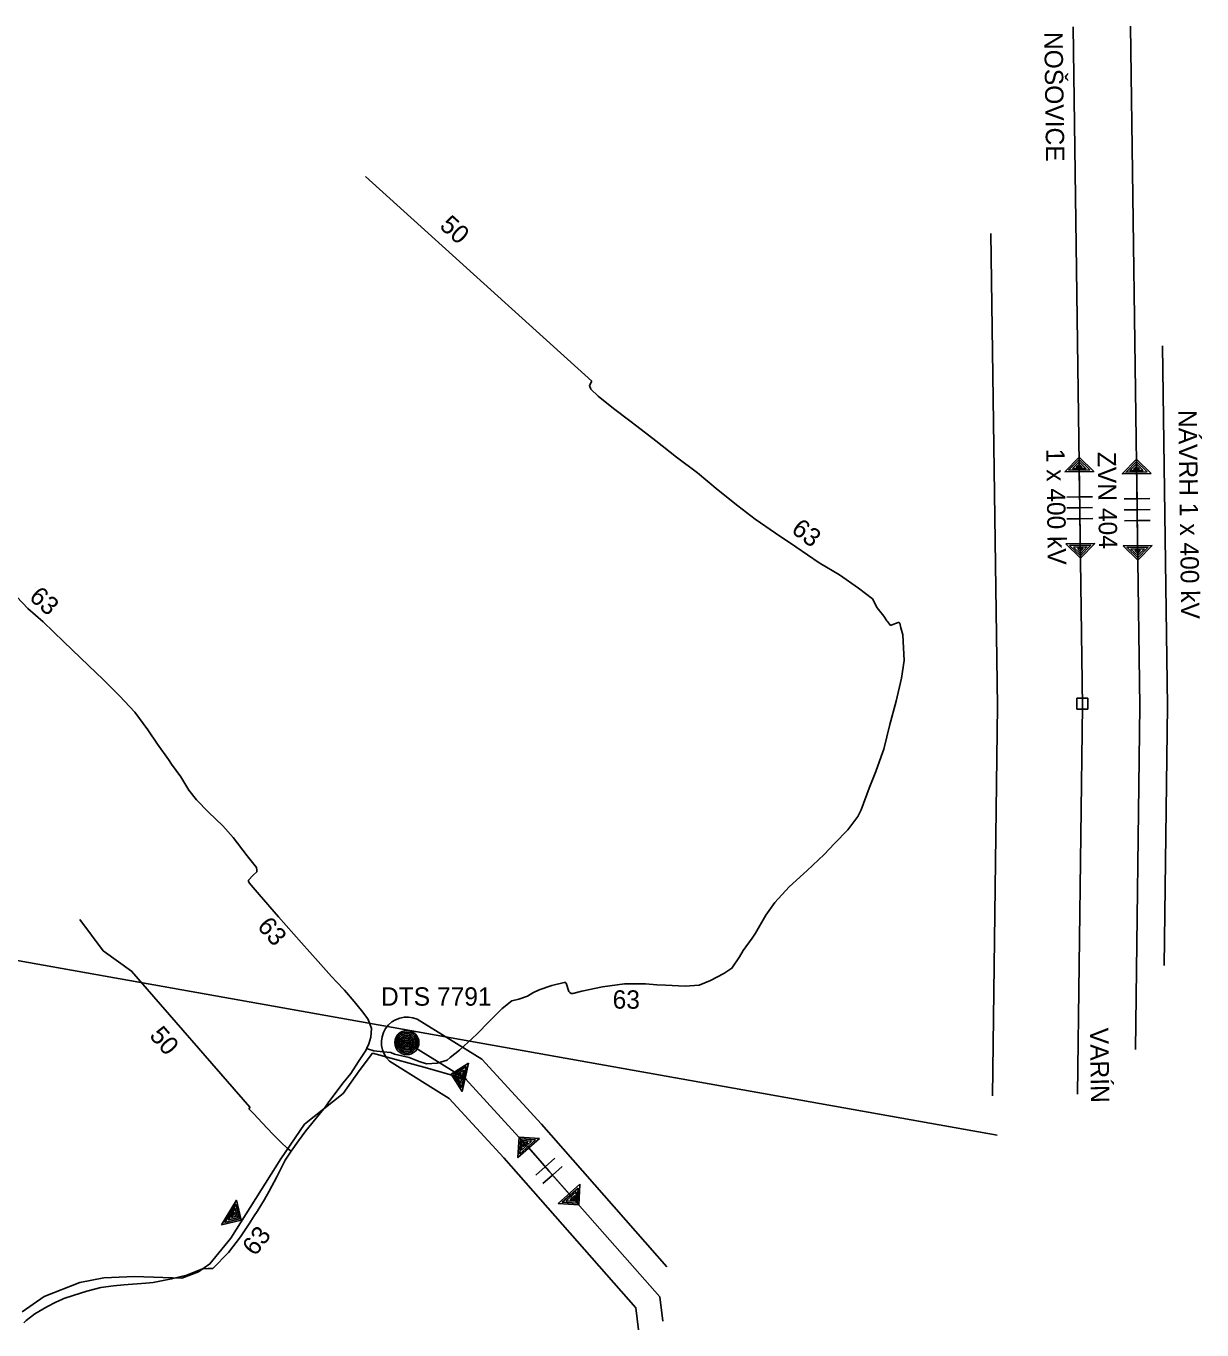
# Model space of a CAD drawing. Extents: x -444841 to -429545, y -1135312 to -1129851.
# Drawn here: x -441113 to -440601, y -1131774 to -1131206 of the extents above; entities that cross this region are included whole.
import ezdxf

# ---------------------------------------------------------------- set-up
doc = ezdxf.new("R2010")
doc.units = 0
for name, color, linetype in [('Vrstva 10', 7, 'Continuous'), ('Vrstva 11', 7, 'Continuous'), ('Vrstva 13', 7, 'Continuous'), ('Vrstva 15', 7, 'Continuous'), ('Vrstva 17', 7, 'Continuous'), ('Vrstva 18', 7, 'Continuous'), ('Vrstva 27', 7, 'Continuous'), ('Vrstva 30', 7, 'Continuous'), ('Vrstva 35', 7, 'Continuous'), ('Vrstva 38', 7, 'Continuous'), ('Vrstva 59', 7, 'Continuous'), ('Vrstva 9', 7, 'Continuous')]:
    doc.layers.add(name, color=color, linetype=linetype)

msp = doc.modelspace()

# ---------------------------------------------------------------- linework, layer by layer
at = {"layer": 'Vrstva 10'}
for p, q in [((-440886.93, -1131702.64), (-440891.13, -1131706.34)), ((-440882.73, -1131698.94), (-440886.93, -1131702.64)), ((-440879.58, -1131702.51), (-440883.79, -1131706.21)), ((-440883.79, -1131706.21), (-440887.99, -1131709.91))]:
    msp.add_line(p, q, dxfattribs=at)
for points in [[(-440835.75, -1131769.83), (-440837.12, -1131759.22), (-440896.8, -1131691.43), (-440921.67, -1131664.33), (-440947.21, -1131648.56)], [(-440894.15, -1131694.44), (-440885.36, -1131704.43), (-440876.57, -1131714.41)]]:
    msp.add_lwpolyline(points, dxfattribs=at)
for points in [[(-440889.42, -1131690.28), (-440898.87, -1131698.6), (-440898.31, -1131689.71)], [(-440891.15, -1131690.87), (-440898.07, -1131696.96), (-440897.65, -1131690.46)], [(-440892.88, -1131691.46), (-440897.26, -1131695.32), (-440897, -1131691.2)], [(-440894.61, -1131692.05), (-440896.46, -1131693.68), (-440896.35, -1131691.94)], [(-440871.84, -1131710.25), (-440872.41, -1131719.14), (-440881.3, -1131718.57)], [(-440872.65, -1131711.89), (-440873.06, -1131718.39), (-440879.57, -1131717.98)], [(-440873.45, -1131713.53), (-440873.72, -1131717.65), (-440877.84, -1131717.39)], [(-440874.26, -1131715.17), (-440874.37, -1131716.91), (-440876.1, -1131716.8)]]:
    msp.add_lwpolyline(points, close=True, dxfattribs=at)
at = {"layer": 'Vrstva 11'}
for radius in [5.25, 4.55, 3.85, 3.15, 2.45, 1.75, 1.05, 0.35]:
    msp.add_circle((-440947.21, -1131648.57), radius, dxfattribs=at)
at = {"layer": 'Vrstva 15'}
for points in [[(-440692.94, -1131296.37), (-440690.11, -1131502.12), (-440692.33, -1131671.75)], [(-440617.58, -1131614.95), (-440616.1, -1131502.09), (-440618.26, -1131345.26)], [(-440833.99, -1131746.13), (-440888.61, -1131684.08), (-440914.59, -1131655.77), (-440942.69, -1131638.42)], [(-440954.79, -1131656.67), (-440928.74, -1131672.89), (-440904.98, -1131698.78), (-440847.6, -1131763.96), (-440846.35, -1131773.63)]]:
    msp.add_lwpolyline(points, dxfattribs=at)
msp.add_arc((-440947.21, -1131648.56), 11.1, 66.0025, 226.9228, dxfattribs=at)
at = {"layer": 'Vrstva 17'}
msp.add_lwpolyline([(-440630.06, -1131651.58), (-440628.11, -1131502.1), (-440632.18, -1131206.12)], dxfattribs=at)
at = {"layer": 'Vrstva 18'}
msp.add_lwpolyline([(-441114.72, -1131765.75), (-441105.1, -1131759.04), (-441089.51, -1131753.06), (-441079.08, -1131750.95), (-441065.74, -1131750.44), (-441045.19, -1131751.17), (-441037.9, -1131748.4), (-441032.95, -1131744.9), (-441023.91, -1131733.68), (-441002.04, -1131699.13), (-440991.84, -1131684.11), (-440974.93, -1131670.7), (-440967.93, -1131660.79), (-440962.1, -1131653.21), (-440938.2, -1131659.63), (-440921.07, -1131664.65)], dxfattribs=at)
for points in [[(-440920.34, -1131657.54), (-440923.19, -1131669.82), (-440927.9, -1131662.26)], [(-440921.41, -1131659.03), (-440923.49, -1131668.01), (-440926.94, -1131662.48)], [(-440922.47, -1131660.52), (-440923.79, -1131666.21), (-440925.97, -1131662.7)], [(-440923.53, -1131662.01), (-440924.09, -1131664.4), (-440925.01, -1131662.93)], [(-441027.92, -1131727.95), (-441021.41, -1131717.16), (-441019.27, -1131725.81)], [(-441026.45, -1131726.86), (-441021.69, -1131718.97), (-441020.12, -1131725.3)], [(-441024.98, -1131725.78), (-441021.96, -1131720.78), (-441020.97, -1131724.79)], [(-441023.51, -1131724.69), (-441022.24, -1131722.59), (-441021.82, -1131724.28)]]:
    msp.add_lwpolyline(points, close=True, dxfattribs=at)
at = {"layer": 'Vrstva 27'}
for points in [[(-440734.19, -1131500), (-440734.17, -1131499.94), (-440731.85, -1131490.01), (-440730.67, -1131482.24), (-440731, -1131476.75), (-440731.26, -1131471.13), (-440732.11, -1131468.09), (-440732.67, -1131466.07), (-440733.01, -1131465.78), (-440733.29, -1131465.73), (-440736.41, -1131466.94), (-440736.74, -1131466.87), (-440737.15, -1131466.45), (-440738.01, -1131465.26), (-440738.28, -1131464.95), (-440739.53, -1131463.02), (-440742.46, -1131459.36), (-440744.56, -1131455.4), (-440750.55, -1131450.74), (-440758.88, -1131445.03), (-440767.75, -1131439.72), (-440777.92, -1131432.84), (-440786.75, -1131426.83), (-440795.64, -1131420.77), (-440803.1, -1131414.95), (-440811.7, -1131408.14), (-440820.7, -1131400.63), (-440829.77, -1131393.74), (-440838.85, -1131386.59), (-440847.1, -1131380.3), (-440850.1, -1131377.96), (-440857.21, -1131372.58), (-440863.95, -1131367.2), (-440867.14, -1131364.23), (-440867.72, -1131362.53), (-440866.7, -1131360.69)], [(-441070.07, -1131500), (-441072.1, -1131497.84), (-441079.4, -1131490.47), (-441085.86, -1131484.44), (-441096.58, -1131474.12), (-441105.52, -1131465.46), (-441112.2, -1131459.56), (-441119.53, -1131451.89), (-441127.19, -1131444.62), (-441136.54, -1131435.94), (-441141.11, -1131431.57), (-441144.33, -1131428.63), (-441149.5, -1131424.16), (-441152.91, -1131420.45), (-441153.4, -1131420.22)], [(-440980.05, -1131619.85), (-440985.79, -1131613.32), (-440993.11, -1131605.08), (-441003.09, -1131593.79), (-441011.45, -1131584.1), (-441015.9, -1131578.99), (-441016.15, -1131578.3), (-441016.1, -1131577.93), (-441014.05, -1131575.74), (-441012.59, -1131574.19), (-441012.57, -1131573.47), (-441012.72, -1131572.41), (-441016.79, -1131567.33), (-441022.87, -1131559.34), (-441027.27, -1131554.29), (-441033.52, -1131548.22), (-441038.78, -1131542.84), (-441042.1, -1131538.7), (-441045.64, -1131532.83), (-441049.64, -1131527.32), (-441050.97, -1131525.3), (-441055.73, -1131518.7), (-441059.92, -1131512.47), (-441065.56, -1131504.81), (-441070.07, -1131500)], [(-440924.34, -1131651.81), (-440916.75, -1131644.88), (-440911.2, -1131639.3), (-440905.77, -1131633.67), (-440901.46, -1131630.43), (-440898.46, -1131629.66), (-440894.65, -1131628.29), (-440892.3, -1131626.92), (-440889.56, -1131625.63), (-440884.1, -1131623.73), (-440878.69, -1131622.39), (-440878.1, -1131622.39), (-440877.88, -1131622.66), (-440876.71, -1131626.32), (-440876.33, -1131626.75), (-440875.66, -1131627.22), (-440874.94, -1131627.22), (-440871.04, -1131626.2), (-440862.11, -1131624.35), (-440852.53, -1131622.95), (-440843.3, -1131623), (-440838.38, -1131623.48), (-440834.57, -1131623.54), (-440826.06, -1131623.95), (-440820.03, -1131623.55), (-440814.97, -1131621.6), (-440809.18, -1131618.53), (-440805.71, -1131616.19), (-440802.36, -1131611.25), (-440800.74, -1131608.52), (-440796.85, -1131603.06), (-440795.42, -1131600.87), (-440790.92, -1131593.16), (-440786.95, -1131587.63), (-440780.72, -1131580.74), (-440772.89, -1131573.68), (-440765.58, -1131566.77), (-440761.07, -1131561.96), (-440755.17, -1131555.96), (-440750.85, -1131550.12), (-440749.48, -1131547.32), (-440745.9, -1131537.81), (-440743.01, -1131530.54), (-440740.73, -1131524.02), (-440739.63, -1131520.88), (-440736.93, -1131510.07), (-440734.19, -1131500)], [(-440964.63, -1131651.04), (-440963.72, -1131649.12), (-440962.86, -1131646.19), (-440962.64, -1131642.43), (-440963.28, -1131640.47), (-440964.23, -1131638.23), (-440967.02, -1131634.58), (-440970.21, -1131630.72), (-440974.33, -1131625.8), (-440977.91, -1131622.07), (-440980.05, -1131619.85)], [(-441113.91, -1131770.51), (-441112.95, -1131769.57), (-441109.22, -1131766.69), (-441103.94, -1131763.55), (-441099.96, -1131761.58), (-441097.42, -1131760.36), (-441096.57, -1131759.96), (-441092.51, -1131758.61), (-441086.55, -1131756.78), (-441085.98, -1131756.61), (-441080.47, -1131755.1), (-441074.98, -1131754.49), (-441070.41, -1131753.99), (-441060.83, -1131753.29), (-441057.65, -1131753.06), (-441049.63, -1131751.45), (-441043.06, -1131749.74), (-441038.37, -1131747.97), (-441036.24, -1131747.02), (-441033.66, -1131746.86), (-441033.5, -1131746.9), (-441031.74, -1131746.83), (-441024.8, -1131739.89), (-441019.64, -1131733.17), (-441015.85, -1131727.48), (-441013.61, -1131723.93), (-441012.41, -1131722.03), (-441009.14, -1131716.84), (-441007.14, -1131713.22), (-441003.88, -1131707.01), (-441000.17, -1131699.7), (-440997.81, -1131696.28), (-440997.52, -1131695.86), (-440994.43, -1131691.31), (-440991.22, -1131687.04), (-440985.36, -1131679.83), (-440983.41, -1131677.42), (-440982.7, -1131676.54), (-440981.14, -1131674.3), (-440974.92, -1131666.11), (-440971.54, -1131661.98), (-440968.19, -1131656.8), (-440965.11, -1131652.06), (-440964.63, -1131651.04)], [(-440964.63, -1131651.04), (-440964.35, -1131651.24), (-440961.6, -1131652.16), (-440957.51, -1131652.63), (-440954.2, -1131652.84), (-440952.54, -1131653.61), (-440946.21, -1131655.08), (-440941.82, -1131656.8), (-440938.59, -1131657.79), (-440933.96, -1131657.52), (-440929.7, -1131656.16), (-440928.29, -1131655.06), (-440926.3, -1131653.52), (-440924.34, -1131651.81)], [(-440997.52, -1131695.86), (-440999.29, -1131694.55), (-441001.92, -1131692.05), (-441005.62, -1131688.41), (-441010.16, -1131683.47), (-441013.86, -1131679.64), (-441015.82, -1131677.54), (-441015.83, -1131677.38), (-441015.67, -1131676.92), (-441015.33, -1131676.51)], [(-441033.66, -1131746.86), (-441033.49, -1131746.69)]]:
    msp.add_lwpolyline(points, dxfattribs=at)
at = {"layer": 'Vrstva 35'}
msp.add_line((-440866.7, -1131360.69), (-440965.19, -1131271.64), dxfattribs=at)
msp.add_lwpolyline([(-441015.52, -1131676.67), (-441067.04, -1131617.45), (-441079.48, -1131608.57), (-441089.54, -1131594.95)], dxfattribs=at)
at = {"layer": 'Vrstva 59'}
msp.add_lwpolyline([(-440690.16, -1131688.83), (-443044.68, -1131269.31), (-443119.43, -1131255.99)], dxfattribs=at)
at = {"layer": 'Vrstva 9'}
for p, q in [((-440659.96, -1131411.1), (-440654.36, -1131411.03)), ((-440654.36, -1131411.03), (-440648.76, -1131410.95)), ((-440629.35, -1131411.87), (-440634.95, -1131411.94)), ((-440623.75, -1131411.79), (-440629.35, -1131411.87)), ((-440659.9, -1131415.86), (-440654.3, -1131415.79)), ((-440654.3, -1131415.79), (-440648.7, -1131415.71)), ((-440629.28, -1131416.63), (-440634.88, -1131416.7)), ((-440623.68, -1131416.55), (-440629.28, -1131416.63)), ((-440659.83, -1131420.62), (-440654.23, -1131420.55)), ((-440654.23, -1131420.55), (-440648.63, -1131420.47)), ((-440629.22, -1131421.39), (-440634.82, -1131421.46)), ((-440623.62, -1131421.31), (-440629.22, -1131421.39))]:
    msp.add_line(p, q, dxfattribs=at)
for points in [[(-440655.32, -1131670.99), (-440653.11, -1131502.1), (-440657.18, -1131206.47)], [(-440654.08, -1131431.46), (-440654.3, -1131415.79), (-440654.51, -1131400.11)], [(-440629.5, -1131400.95), (-440629.28, -1131416.63), (-440629.07, -1131432.3)]]:
    msp.add_lwpolyline(points, dxfattribs=at)
for points in [[(-440660.81, -1131400.19), (-440654.6, -1131393.81), (-440648.21, -1131400.02)], [(-440659.13, -1131399.47), (-440654.59, -1131394.8), (-440649.91, -1131399.34)], [(-440657.45, -1131398.75), (-440654.57, -1131395.79), (-440651.61, -1131398.67)], [(-440655.77, -1131398.02), (-440654.56, -1131396.78), (-440653.31, -1131397.99)], [(-440623.2, -1131400.86), (-440635.8, -1131401.03), (-440629.59, -1131394.65)], [(-440624.9, -1131400.18), (-440634.12, -1131400.31), (-440629.57, -1131395.64)], [(-440626.6, -1131399.51), (-440632.44, -1131399.59), (-440629.56, -1131396.63)], [(-440628.3, -1131398.83), (-440630.76, -1131398.86), (-440629.54, -1131397.62)], [(-440660.38, -1131431.55), (-440647.78, -1131431.38), (-440653.99, -1131437.76)], [(-440658.68, -1131432.23), (-440649.46, -1131432.1), (-440654.01, -1131436.77)], [(-440656.98, -1131432.9), (-440651.14, -1131432.82), (-440654.02, -1131435.78)], [(-440655.28, -1131433.58), (-440652.82, -1131433.55), (-440654.03, -1131434.79)], [(-440622.77, -1131432.22), (-440628.98, -1131438.6), (-440635.37, -1131432.39)], [(-440624.45, -1131432.94), (-440628.99, -1131437.61), (-440633.67, -1131433.07)], [(-440626.13, -1131433.66), (-440629.01, -1131436.62), (-440631.97, -1131433.74)], [(-440627.81, -1131434.39), (-440629.02, -1131435.63), (-440630.27, -1131434.42)], [(-440655.52, -1131503.39), (-440650.79, -1131503.39), (-440650.79, -1131498.66), (-440655.52, -1131498.66)]]:
    msp.add_lwpolyline(points, close=True, dxfattribs=at)

# ---------------------------------------------------------------- texts
at = {"layer": 'Vrstva 13'}
for s, p in [('NOŠOVICE', (-440669.73, -1131208.73)), ('NÁVRH 1 x 400 kV', (-440611.35, -1131373.27)), ('1 x 400 kV', (-440668.86, -1131390.1)), ('ZVN 404', (-440646.5, -1131391.52)), ('VARÍN', (-440649.83, -1131642.15))]:
    msp.add_text(s, height=8, rotation=270.7889, dxfattribs=at).set_placement(p)
msp.add_text('DTS 7791', height=8, dxfattribs=at).set_placement((-440958.48, -1131632.51))
at = {"layer": 'Vrstva 30'}
for rotation, p in [(322.778, (-440780.33, -1131426.23)), (318.548, (-441112.09, -1131455.32)), (311.4757, (-441012.72, -1131598.24)), (359.6896, (-440857.66, -1131633.78)), (52.4863, (-441013.2, -1131741.88))]:
    msp.add_text('63', height=8, rotation=rotation, dxfattribs=at).set_placement(p)
at = {"layer": 'Vrstva 38'}
for rotation, p in [(317.8804, (-440933.39, -1131293.65)), (311.0233, (-441059.64, -1131645.77))]:
    msp.add_text('50', height=8, rotation=rotation, dxfattribs=at).set_placement(p)

doc.saveas('drawing.dxf')
